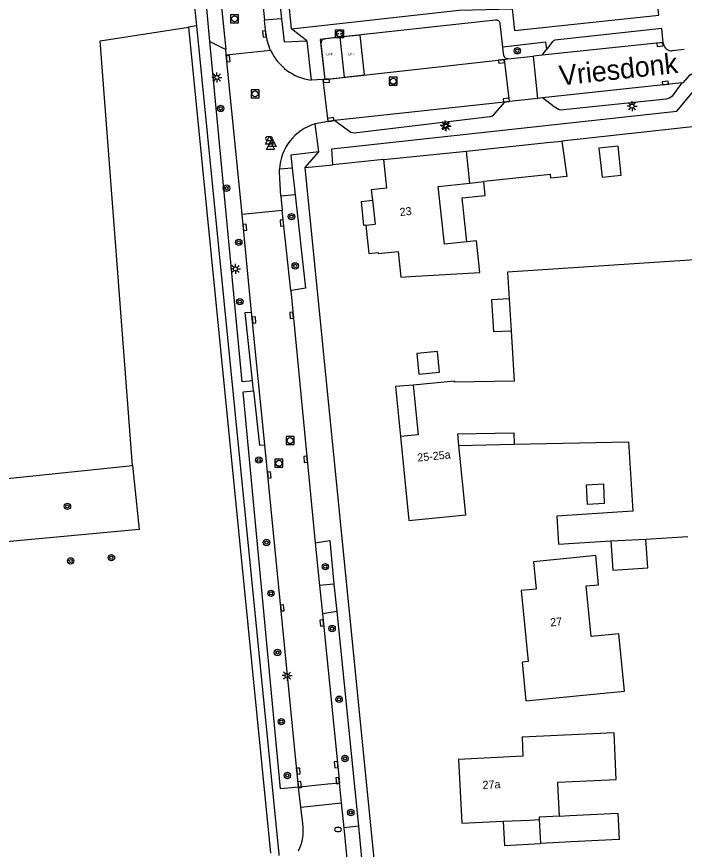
# Model space of a CAD drawing. Extents: x 140000 to 143000, y 403500 to 406000.
# Drawn here: x 140523.7 to 140607.1, y 403984.8 to 404088.8 of the extents above; entities that cross this region are included whole.
import ezdxf

# ---------------------------------------------------------------- set-up
doc = ezdxf.new("R2010")
doc.units = 0
for name, color, linetype in [('bp-grn-parkeervak', 7, 'Continuous'), ('gg-afsc-hekwerk', 7, 'Continuous'), ('gg-anno-huisnummerreeks BGT', 7, 'Continuous'), ('gg-anno-openbare ruimte label', 7, 'Continuous'), ('gg-bbg-bijgebouw', 7, 'Continuous'), ('gg-bbg-hoofdgebouw', 7, 'Continuous'), ('gg-bbg-luifel en loopbrug', 7, 'Continuous'), ('gg-bbg-overig bouwwerk', 7, 'Continuous'), ('gg-bbg-tussenscheiding', 7, 'Continuous'), ('gg-knt-verharding', 7, 'Continuous'), ('gg-knt-verharding nz', 7, 'Continuous'), ('gt-grn-groengrens', 7, 'Continuous'), ('gt-symb-boom', 7, 'Continuous'), ('gt-symb-brandkraan', 7, 'Continuous'), ('gt-symb-kolk', 7, 'Continuous'), ('gt-symb-laadpunt elektrisch vervoer', 7, 'Continuous'), ('gt-symb-lichtmast', 7, 'Continuous'), ('gt-symb-rioolschacht', 7, 'Continuous'), ('gt-symb-waterafsluiter', 7, 'Continuous'), ('kenmerkpunt laadpunt parkeerplaats', 7, 'Continuous')]:
    doc.layers.add(name, color=color, linetype=linetype)

# ---------------------------------------------------------------- blocks, each defined once
blk = doc.blocks.new('gt0-KOLK')
at = {"layer": 'gt-symb-kolk'}
blk.add_lwpolyline([(0, 0), (0.38, 0), (0.38, 0.4), (-0.37, 0.4), (-0.37, 0), (0, 0)], dxfattribs=at)
blk = doc.blocks.new('gt0-RS')
at = {"layer": 'gt-symb-rioolschacht'}
blk.add_lwpolyline([(-0.5, -0.5), (0.5, -0.5), (0.5, 0.5), (-0.5, 0.5)], close=True, dxfattribs=at)
blk.add_circle((0, 0), 0.375, dxfattribs=at)
blk = doc.blocks.new('gt0-LEV')
at = {"layer": 'gt-symb-laadpunt elektrisch vervoer'}
blk.add_lwpolyline([(-0.49, 0.5), (0.49, 0.5), (0.49, -0.5), (-0.49, -0.5)], close=True, dxfattribs=at)
for centre, radius in [((0, 0), 0.393), ((-0.19, 0), 0.0566), ((0.19, 0), 0.0566)]:
    blk.add_circle(centre, radius, dxfattribs=at)
blk = doc.blocks.new('gt0-LMAST')
at = {"layer": 'gt-symb-lichtmast'}
for p, q in [((-0.18, 0.17), (-0.45, 0.44)), ((-0.01, 0.25), (-0.01, 0.62)), ((0.17, 0.17), (0.44, 0.44)), ((-0.26, 0), (-0.63, 0)), ((-0.18, -0.18), (-0.45, -0.45)), ((-0.01, -0.25), (-0.01, -0.63)), ((0.44, -0.45), (0.17, -0.18)), ((0.24, 0), (0.62, 0))]:
    blk.add_line(p, q, dxfattribs=at)
blk.add_circle((-0.01, 0), 0.25, dxfattribs=at)
blk = doc.blocks.new('gt0-WAFSL')
at = {"layer": 'gt-symb-waterafsluiter'}
for p, q in [((-0.5, -0.33), (0, 0.67)), ((0, 0.67), (0.5, -0.33)), ((0.5, -0.33), (-0.5, -0.33))]:
    blk.add_line(p, q, dxfattribs=at)
blk = doc.blocks.new('gt0-BR')
at = {"layer": 'gt-symb-brandkraan'}
for centre, radius, start, end in [((-0.24, 0), 0.206, 107.5669, 252.4331), ((0.6, -2.66), 3, 106.892, 107.5669), ((0, -0.69), 0.938, 73.108, 106.892), ((-0.6, -2.66), 3, 72.4331, 73.108), ((0.24, 0), 0.206, 287.567, 72.4331), ((0.6, 2.66), 3, 252.4331, 253.108), ((0, 0.69), 0.938, 253.108, 286.8921), ((-0.6, 2.66), 3, 286.8921, 287.567)]:
    blk.add_arc(centre, radius, start, end, dxfattribs=at)
blk = doc.blocks.new('gt0-BOOM')
at = {"layer": 'gt-symb-boom'}
for radius in [0.4, 0.2]:
    blk.add_circle((0, 0), radius, dxfattribs=at)

msp = doc.modelspace()

# ---------------------------------------------------------------- linework, layer by layer
at = {"layer": 'bp-grn-parkeervak'}
msp.add_line((140564.67, 404081.25), (140564.11, 404086.24), dxfattribs=at)
for points in [[(140564.11, 404086.24), (140561.63, 404085.96), (140562.18, 404080.97), (140564.67, 404081.25)], [(140564.67, 404081.25), (140567.15, 404081.52), (140566.6, 404086.51), (140564.11, 404086.24)]]:
    msp.add_lwpolyline(points, dxfattribs=at)
at = {"layer": 'gg-afsc-hekwerk'}
msp.add_line((140569.5, 404070.95), (140563.21, 404070.29), dxfattribs=at)
at = {"layer": 'gg-bbg-bijgebouw'}
for p, q in [((140580.3, 404068.03), (140582.04, 404068.22)), ((140588.97, 403988.55), (140589.11, 403985.56))]:
    msp.add_line(p, q, dxfattribs=at)
for points in [[(140579.87, 404072), (140589.95, 404073.07), (140591.8, 404073.27)], [(140591.8, 404073.27), (140592.42, 404068.84), (140590.42, 404068.63), (140590.37, 404069.1), (140582.04, 404068.22)], [(140576.49, 404044.42), (140576.27, 404046.98), (140573.68, 404046.74), (140573.91, 404044.18), (140576.49, 404044.42)], [(140591.49, 403988.98), (140592.8, 403989.04), (140598.79, 403989.34), (140598.95, 403986.04), (140592.96, 403985.75), (140589.11, 403985.56)]]:
    msp.add_lwpolyline(points, dxfattribs=at)
at = {"layer": 'gg-bbg-hoofdgebouw'}
for p, q in [((140569.5, 404070.95), (140579.87, 404072)), ((140568.13, 404065.89), (140568.46, 404062.88)), ((140567.31, 404062.76), (140568.46, 404062.88)), ((140585.21, 404053.56), (140585.46, 404049.57)), ((140602.27, 404023.55), (140607.49, 404023.9)), ((140597.89, 404023.35), (140602.27, 404023.55))]:
    msp.add_line(p, q, dxfattribs=at)
for points in [[(140569.5, 404070.95), (140569.89, 404067.4), (140567.99, 404067.19), (140568.13, 404065.89)], [(140579.94, 404060.7), (140577.12, 404060.39), (140576.33, 404067.61), (140580.3, 404068.03)], [(140567.31, 404062.76), (140567.68, 404059.24), (140568.84, 404059.36)], [(140568.84, 404059.36), (140568.86, 404059.22), (140571.35, 404059.49), (140571.68, 404056.27), (140572.85, 404056.34), (140581.53, 404056.84), (140581.12, 404060.83), (140579.94, 404060.7)], [(140617.24, 404059.04), (140585.01, 404056.89), (140585.21, 404053.56)], [(140585.46, 404049.57), (140585.84, 404043.29), (140578.39, 404043.16), (140578.38, 404043.3), (140573.24, 404042.78)], [(140573.24, 404042.78), (140573.86, 404036.59), (140571.65, 404036.37)], [(140571.65, 404036.37), (140572.69, 404025.89), (140579.8, 404026.61), (140578.94, 404035.27)], [(140578.94, 404035.27), (140578.8, 404036.72), (140585.8, 404036.84), (140585.83, 404035.41)], [(140585.83, 404035.41), (140600.11, 404035.7), (140600.65, 404027.05), (140591.15, 404026.43), (140591.38, 404022.92), (140597.89, 404023.35)], [(140596.37, 404017.87), (140596.02, 404021.5), (140593.22, 404021.22), (140588.25, 404020.72), (140588.59, 404017.33), (140586.7, 404017.14), (140587.57, 404008.28), (140586.84, 404008.21), (140587.29, 404003.39), (140596.14, 404004.24), (140599.61, 404004.58), (140598.91, 404011.73), (140595.44, 404011.39), (140594.82, 404017.72), (140596.37, 404017.87)], [(140591.49, 403988.98), (140591.29, 403993.03), (140591.28, 403993.23), (140598.57, 403993.57), (140598.3, 403999.37), (140586.81, 403998.83), (140586.92, 403996.46), (140578.9, 403996.06), (140579.28, 403988.1), (140584.47, 403988.34)], [(140584.47, 403988.34), (140587.78, 403988.49), (140588.97, 403988.55)]]:
    msp.add_lwpolyline(points, dxfattribs=at)
at = {"layer": 'gg-bbg-luifel en loopbrug'}
msp.add_line((140578.94, 404035.27), (140585.83, 404035.41), dxfattribs=at)
for points in [[(140579.94, 404060.7), (140579.34, 404066.18), (140582.23, 404066.49), (140582.04, 404068.22)], [(140567.31, 404062.76), (140567.08, 404062.73), (140566.78, 404065.74), (140568.13, 404065.89)], [(140585.21, 404053.56), (140583.02, 404053.46), (140583.27, 404049.47), (140585.46, 404049.57)], [(140573.24, 404042.78), (140571.02, 404042.61), (140571.65, 404036.37)], [(140594.94, 404027.93), (140597.12, 404028.04), (140597.01, 404030.41), (140594.82, 404030.3), (140594.94, 404027.93)], [(140584.47, 403988.34), (140584.62, 403985.33), (140589.11, 403985.56)]]:
    msp.add_lwpolyline(points, dxfattribs=at)
at = {"layer": 'gg-bbg-overig bouwwerk'}
for points in [[(140596.8, 404068.76), (140599.2, 404069.02), (140598.8, 404072.63), (140596.4, 404072.37), (140596.8, 404068.76)], [(140597.89, 404023.35), (140598.13, 404019.67), (140602.5, 404019.96), (140602.27, 404023.55)]]:
    msp.add_lwpolyline(points, dxfattribs=at)
at = {"layer": 'gg-bbg-tussenscheiding'}
msp.add_line((140580.3, 404068.03), (140579.87, 404072), dxfattribs=at)
msp.add_lwpolyline([(140591.49, 403988.98), (140588.96, 403988.85), (140588.97, 403988.55)], dxfattribs=at)
at = {"layer": 'gg-knt-verharding'}
for p, q in [((140547.86, 404085.69), (140546.59, 404099.15)), ((140545.08, 404098.58), (140546.16, 404087.64)), ((140553.89, 404096.01), (140554.67, 404088.36)), ((140555.95, 404096.21), (140556.79, 404088.53)), ((140554.84, 404086.69), (140554.67, 404088.36)), ((140583.51, 404088.36), (140562.15, 404086.02)), ((140546.16, 404087.64), (140545.17, 404087.49)), ((140559.94, 404085.8), (140558.03, 404087.3)), ((140584.41, 404084.99), (140584.08, 404087.93)), ((140547.86, 404085.69), (140549.83, 404084.71)), ((140559.94, 404085.8), (140560.47, 404080.87)), ((140561.71, 404085.46), (140562.18, 404080.97)), ((140604.46, 404085.41), (140604.44, 404085.55)), ((140549.89, 404084.05), (140549.83, 404084.71)), ((140549.89, 404084.05), (140555.42, 404084.6)), ((140589.34, 404083.98), (140589.9, 404084.74)), ((140607.07, 404084.69), (140605.57, 404084.52)), ((140562.18, 404080.97), (140584.6, 404083.47)), ((140584.6, 404083.47), (140585.03, 404083.52)), ((140584.6, 404083.47), (140585.19, 404078.2)), ((140585.03, 404083.52), (140588.23, 404083.86)), ((140589.34, 404083.98), (140588.23, 404083.86)), ((140588.79, 404078.59), (140588.23, 404083.86)), ((140561.98, 404080.96), (140560.47, 404080.87)), ((140562.18, 404080.97), (140561.98, 404080.96)), ((140562.61, 404075.7), (140561.98, 404080.96)), ((140606.78, 404080.55), (140589.35, 404078.65)), ((140584.61, 404078.14), (140563.4, 404075.83)), ((140585.19, 404078.2), (140584.61, 404078.14)), ((140588.79, 404078.59), (140585.19, 404078.2)), ((140589.35, 404078.65), (140588.79, 404078.59)), ((140563.4, 404075.83), (140562.61, 404075.7)), ((140560.99, 404075.41), (140560.97, 404075.41)), ((140562.61, 404075.7), (140560.99, 404075.41)), ((140561.44, 404071.91), (140560.99, 404075.41)), ((140559.76, 404069.98), (140561.44, 404071.91)), ((140569.5, 404070.95), (140563.21, 404070.29)), ((140558.13, 404069.87), (140556.54, 404069.77)), ((140558.13, 404069.87), (140558.48, 404066.57)), ((140559.76, 404069.98), (140563.21, 404070.29)), ((140604.37, 403622.98), (140559.76, 404069.98)), ((140558.48, 404066.57), (140556.69, 404066.4)), ((140556.69, 404066.4), (140556.88, 404064.61)), ((140556.88, 404064.61), (140551.86, 404064.11)), ((140557.95, 404054.61), (140556.88, 404064.61)), ((140553.06, 404051.92), (140551.86, 404064.11)), ((140557.95, 404054.61), (140561, 404023.12)), ((140554.69, 404035.35), (140553.06, 404051.92)), ((140553.29, 404042.1), (140553.15, 404043.34)), ((140558.89, 403992.61), (140554.69, 404035.35)), ((140561, 404023.12), (140561.54, 404017.78)), ((140563.32, 404017.96), (140561.54, 404017.78)), ((140563.32, 404017.96), (140563.71, 404014.51)), ((140563.71, 404014.51), (140561.9, 404014.23)), ((140563.71, 404014.51), (140566.39, 403987.71)), ((140561.9, 404014.23), (140564.03, 403993.15)), ((140559.2, 403990.11), (140558.89, 403992.61)), ((140564.28, 403990.63), (140564.03, 403993.15)), ((140559.2, 403990.11), (140564.28, 403990.63)), ((140564.6, 403987.53), (140564.28, 403990.63)), ((140559.45, 403988.06), (140559.2, 403990.11)), ((140566.39, 403987.71), (140564.6, 403987.53)), ((140566.39, 403987.71), (140567.37, 403977.8))]:
    msp.add_line(p, q, dxfattribs=at)
for points in [[(140558.03, 404087.3), (140550.27, 404165.24), (140549.76, 404170.42), (140549.44, 404173.58), (140549.12, 404176.86), (140547.3, 404195.13), (140547.02, 404197.87), (140545.89, 404209.33), (140545.42, 404213.99), (140543.99, 404228.36), (140538.54, 404282.69)], [(140585.6, 404089.79), (140585.89, 404087.06), (140603.87, 404089), (140603.74, 404090.44)], [(140558.03, 404087.3), (140578.96, 404089.6), (140585.6, 404089.79)], [(140556.79, 404088.53), (140557.1, 404085.66), (140559.94, 404085.8)], [(140538.19, 404032.74), (140534.17, 404085.77), (140545.17, 404087.49)], [(140546.16, 404087.64), (140556.45, 403984.21), (140556.46, 403984.07)], [(140604.44, 404085.55), (140604.27, 404087.33), (140590.91, 404085.88)], [(140553.15, 404043.34), (140551.88, 404043.19), (140547.86, 404085.69)], [(140589.9, 404084.74), (140589.79, 404085.62), (140584.41, 404084.99)], [(140590.91, 404085.88), (140590.61, 404085.68), (140589.9, 404084.74)], [(140585.03, 404083.52), (140584.7, 404083.62), (140584.53, 404083.93), (140584.41, 404084.99)], [(140551.86, 404064.11), (140551.29, 404069.98), (140549.89, 404084.05)], [(140606.78, 404080.55), (140606.97, 404080.57), (140607.79, 404081.52), (140608.33, 404081.85), (140615.97, 404082.64), (140632.75, 404081.08)], [(140606.78, 404080.55), (140605.56, 404078.89), (140605.32, 404078.68), (140604.81, 404078.5), (140591.6, 404077.12), (140591.44, 404077.18), (140590.82, 404077.54), (140589.35, 404078.65)], [(140615.7, 404080.63), (140616.05, 404075.93), (140591.8, 404073.27)], [(140563.21, 404070.29), (140563.06, 404072.29), (140606.12, 404077), (140608.45, 404079.79), (140608.79, 404077.91)], [(140584.61, 404078.14), (140583.08, 404076.38), (140582.81, 404076.28), (140565.87, 404074.26), (140565.44, 404074.35), (140564.71, 404074.86), (140563.4, 404075.83)], [(140561.44, 404071.91), (140557.96, 404071.52), (140558.13, 404069.87)], [(140556.69, 404066.4), (140556.53, 404069.34), (140556.54, 404069.77)], [(140558.48, 404066.57), (140559.8, 404054.89), (140558.02, 404054.62), (140557.95, 404054.61)], [(140558.89, 403992.61), (140556.68, 403992.37), (140552, 404041.97), (140553.29, 404042.1)], [(140538.19, 404032.74), (140539.02, 404024.78), (140427.5, 404014.39), (140427.06, 404019.11)], [(140463.7, 404027.03), (140468.4, 404025.5), (140538.19, 404032.74)], [(140561, 404023.12), (140562.83, 404023.4), (140563.32, 404017.96)], [(140558.89, 403992.61), (140559.05, 403992.63), (140562.59, 403993.01), (140564.03, 403993.15)]]:
    msp.add_lwpolyline(points, dxfattribs=at)
for centre, radius, start, end in [((140583.61, 404087.9), 0.472, 3.0179, 101.5129), ((140561.35, 404087.36), 6.55, 185.8692, 204.9786), ((140562.21, 404085.51), 0.505, 96.9671, 186.3927), ((140605.49, 404085.56), 1.04, 188.4203, 274.26), ((140561.36, 404087.36), 6.55, 204.9594, 262.1953), ((140562.76, 404069.43), 6.24, 106.6788, 176.9216), ((140553.47, 403987.25), 6.04, 334.253, 7.6851)]:
    msp.add_arc(centre, radius, start, end, dxfattribs=at)
at = {"layer": 'gg-knt-verharding nz'}
for p, q in [((140548.27, 404100.35), (140549.83, 404084.71)), ((140561.54, 404017.78), (140561.9, 404014.23)), ((140565.59, 403977.65), (140564.6, 403987.53))]:
    msp.add_line(p, q, dxfattribs=at)
msp.add_lwpolyline([(140604.44, 404085.55), (140604.01, 404085.52), (140589.34, 404083.98)], dxfattribs=at)
at = {"layer": 'gt-grn-groengrens'}
for p, q in [((140556.79, 404088.53), (140554.67, 404088.36)), ((140545.17, 404087.49), (140555.43, 403984.34))]:
    msp.add_line(p, q, dxfattribs=at)
for points in [[(140553.15, 404043.34), (140552.24, 404051.86), (140553.06, 404051.92)], [(140553.29, 404042.1), (140554.02, 404035.29), (140554.69, 404035.35)]]:
    msp.add_lwpolyline(points, dxfattribs=at)

# ---------------------------------------------------------------- block references
at = {"layer": 'gt-symb-boom'}
for p in [(140586.23, 404084.54), (140549.19, 404077.34), (140549.92, 404067.39), (140558.03, 404063.83), (140551.45, 404060.62), (140558.5, 404057.68), (140551.58, 404053.21), (140553.96, 404033.44), (140530.06, 404027.66), (140554.91, 404023.13), (140530.47, 404020.84), (140535.55, 404021.25), (140562.26, 404020.12), (140555.48, 404016.8), (140563.1, 404012.4), (140556.29, 404009.41), (140563.98, 404003.57), (140556.76, 404000.77), (140564.71, 403996.17), (140557.52, 403994.05), (140565.43, 403989.43)]:
    msp.add_blockref('gt0-BOOM', p, dxfattribs=at)
at = {"layer": 'gt-symb-brandkraan'}
for p in [(140555.22, 404073.57), (140563.83, 403987.31)]:
    msp.add_blockref('gt0-BR', p, dxfattribs=at)
at = {"layer": 'gt-symb-kolk'}
for p, rotation in [((140554.85, 404086.66), 95.80373342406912), ((140604.01, 404085.52), -174.02521005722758), ((140549.94, 404083.55), -84.33357256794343), ((140584.23, 404083.43), -173.62772575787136), ((140562.36, 404080.99), -175.13582774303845), ((140604.71, 404080.32), 6.2020525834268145), ((140584.86, 404078.17), 6.218098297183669), ((140562.98, 404075.76), 9.885509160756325), ((140557.04, 404063.05), 96.10404125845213), ((140552.02, 404062.47), -84.39058213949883), ((140558.25, 404051.51), 95.5283174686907), ((140553.16, 404050.92), -84.39058213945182), ((140559.99, 404033.53), 95.5283174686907), ((140555.06, 404031.57), -84.39058213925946), ((140556.69, 404014.97), -84.39058213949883), ((140562.01, 404013.11), 95.77964834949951), ((140563.8, 403995.43), 95.77964834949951), ((140558.7, 403994.58), -84.73104906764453), ((140564, 403993.43), 95.77964834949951), ((140558.86, 403992.9), -83.24632052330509)]:
    msp.add_blockref('gt0-KOLK', p, dxfattribs=dict(at, rotation=rotation))
at = {"layer": 'gt-symb-laadpunt elektrisch vervoer'}
msp.add_blockref('gt0-LEV', (140564.03, 404086.67), dxfattribs=at)
at = {"layer": 'gt-symb-lichtmast'}
for p in [(140548.73, 404081.21), (140600.55, 404077.63), (140577.24, 404075.23), (140577.33, 404075.12), (140551.05, 404057.3), (140557.49, 404006.52)]:
    msp.add_blockref('gt0-LMAST', p, dxfattribs=at)
at = {"layer": 'gt-symb-rioolschacht'}
for p in [(140550.93, 404088.53), (140570.73, 404080.73), (140553.48, 404079.16), (140557.86, 404035.87), (140556.46, 404033.03)]:
    msp.add_blockref('gt0-RS', p, dxfattribs=at)
at = {"layer": 'gt-symb-waterafsluiter'}
for p in [(140555.29, 404073.22), (140555.41, 404072.53), (140555.62, 404072.92)]:
    msp.add_blockref('gt0-WAFSL', p, dxfattribs=at)

# ---------------------------------------------------------------- texts
at = {"layer": 'gg-anno-huisnummerreeks BGT'}
for s, rotation, p in [('23', 6.2, (140571.59, 404063.9)), ('25-25a', 5.6, (140573.79, 404033.24)), ('27', 5.6, (140590.38, 404012.66)), ('27a', 2.7, (140581.91, 403992.37))]:
    msp.add_text(s, height=1, rotation=rotation, dxfattribs=at).set_placement(p)
at = {"layer": 'gg-anno-openbare ruimte label'}
msp.add_text('Vriesdonk', height=2.5, rotation=6.2, dxfattribs=at).set_placement((140591.58, 404080.19))
at = {"layer": 'kenmerkpunt laadpunt parkeerplaats'}
for p in [(140562.41, 404083.97), (140565.11, 404083.98)]:
    msp.add_text('LPP', height=0.3, dxfattribs=at).set_placement(p)

doc.saveas('drawing.dxf')
